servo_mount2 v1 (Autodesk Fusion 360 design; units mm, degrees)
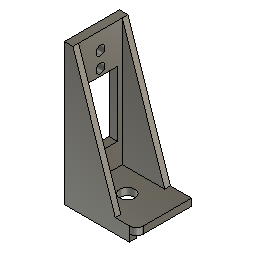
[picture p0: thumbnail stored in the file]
sketch "Sketch1" plane through (0, 0, 0) normal (0, 0, 1) x axis (1, 0, 0)
  line L1 (-10.25, 8.5) -> (10.25, 8.5)
  line L2 (-10.25, -8.5) -> (-10.25, 8.5)
  line L3 (10.25, -8.5) -> (-10.25, -8.5)
  line L4 (10.25, 8.5) -> (10.25, -8.5)
  line L5 (-10.25, -8.5) -> (10.25, 8.5)
  line L6 (10.25, -8.5) -> (-10.25, 8.5)
  point P6 (0, 0)
  point P1 (0, 0)
  point P2 (10.25, 8.5)
  point P5 (10.25, -8.5)
  point P4 (-10.25, -8.5)
  horizontal L1
  perpendicular L1 L2
  parallel L1 L3
  parallel L2 L4
  coincident L5 P6
  coincident L6 P6
  coincident P1 P6
  dimension "d1" distance P2 P5 = 17
  dimension "d2" distance P4 P5 = 20.5
extrude "Extrude1" new body sketch "Sketch1" profile of L1 L2 L3 L4 along normal blind 2.5
shell "Shell1" outerThickness 2.5
fillet "Fillet1" radius 2.5 1
sketch "Sketch2" plane through (0, 0, 2.5) normal (0, 0, -1) x axis (1, 0, 0)
  line L1 (-10.25, -8.5) -> (-10.25, 7.5)
  line L2 (10.25, -8.5) -> (-10.25, -8.5)
  line L3 (10.25, 7.5) -> (10.25, -8.5)
  line L4 (-9.25, 8.5) -> (9.25, 8.5)
  arc A1 centre (-9.25, 7.5) radius 1 clockwise from (-10.25, 7.5) to (-9.25, 8.5)
  arc A2 centre (9.25, 7.5) radius 1 clockwise from (9.25, 8.5) to (10.25, 7.5)
  circle C1 centre (0, 1.5) radius 2.7
  point P1 (0, 0)
  point P10 (0, 1.5)
  vertical P1 P10
  dimension "d10" diameter C1 = 5.4
  dimension "d11" distance L4 P10 = 7
extrude "Extrude2" cut sketch "Sketch2" profile of C1 against normal blind 7
sketch "Sketch3" plane through (-12.75, 0, 0) normal (-1, 0, 0) x axis (0, -1, 0)
  line L1 (11, 0) -> (-8.5, 0)
  line L2 (11, 5) -> (11, 0)
  line L3 (-8.5, 5) -> (11, 5)
  line L4 (-8.5, 0) -> (-8.5, 5)
  line L5 (-8.5, 5) -> (11, 5)
  line L6 (-8.5, 50) -> (-8.5, 5)
  line L7 (11, 50) -> (-8.5, 50)
  line L8 (11, 5) -> (11, 50)
  point P4 (11, 5)
  point P6 (11, 5)
  point P5 (-8.5, 5)
  point P7 (-8.5, 5)
  point P9 (11, 50)
  horizontal L5
  vertical L6
  horizontal L7
  vertical L8
  coincident P4 P6
  coincident P5 P7
  dimension "d14" distance P6 P9 = 45
extrude "Extrude3" add sketch "Sketch3" profile of L3 L5 L6 L7 L8 against normal blind 3
sketch "Sketch4" plane through (0, -11, 0) normal (0, -1, 0) x axis (1, 0, 0)
  line L1 (10.25, 5) -> (10.25, 0)
  line L2 (-9.75, 5) -> (10.25, 5)
  line L3 (-9.75, 50) -> (-9.75, 5)
  line L4 (-12.75, 50) -> (-9.75, 50)
  line L5 (-12.75, 0) -> (-12.75, 50)
  line L6 (10.25, 0) -> (-12.75, 0)
  line L7 (-9.75, 50) -> (5.25, 5)
  point P8 (5.25, 5)
  point P5 (-9.75, 50)
  point P9 (-9.75, 50)
  coincident L2 P8
  coincident P5 P9
  dimension "d17" distance P8 P9 = 15
extrude "Extrude4" add sketch "Sketch4" profile of L2 L3 L7 against normal blind 2
sketch "Sketch5" plane through (0, 8.5, 0) normal (0, 1, 0) x axis (-1, 0, 0)
  line L1 (-10.25, 2.5) -> (-10.25, 0)
  line L2 (10.25, 2.5) -> (-10.25, 2.5)
  line L3 (10.25, 0) -> (10.25, 2.5)
  line L4 (12.75, 0) -> (10.25, 0)
  line L5 (12.75, 50) -> (12.75, 0)
  line L6 (9.75, 50) -> (12.75, 50)
  line L7 (9.75, 5) -> (9.75, 50)
  line L8 (-12.75, 5) -> (9.75, 5)
  line L9 (-12.75, 0) -> (-12.75, 5)
  line L10 (-10.25, 0) -> (-12.75, 0)
  line L11 (9.75, 5) -> (-5.25, 5)
  line L12 (9.75, 50) -> (9.75, 5)
  line L13 (-5.25, 5) -> (9.75, 50)
extrude "Extrude5" add sketch "Sketch5" profile of L7 L8 L11 L12 L13 against normal blind 2
sketch "Sketch6" plane through (-9.75, 0, 0) normal (1, 0, 0) x axis (0, 1, 0)
  line L1 (6.5, 50) -> (6.5, 5)
  line L2 (-9, 50) -> (6.5, 50)
  line L3 (-9, 5) -> (-9, 50)
  line L4 (6.5, 5) -> (-9, 5)
  line L5 (4.8, 36) -> (-7.3, 36)
  line L6 (4.8, 13) -> (4.8, 36)
  line L7 (-7.3, 13) -> (4.8, 13)
  line L8 (-7.3, 36) -> (-7.3, 13)
  line L9 (-9, 5) -> (6.5, 5)
  circle C1 centre (-1.25, 38.4) radius 1.6
  circle C2 centre (-1.25, 10.6) radius 1.6
  circle C3 centre (-1.25, 18.9) radius 1.5
  circle C4 centre (-1.25, 43.9) radius 1.6
  point P10 (-1.25, 13)
  point P13 (-1.25, 5)
  point P15 (-1.25, 36)
  point P16 (4.8, 24.5)
  point P14 (-1.25, 38.4)
  point P17 (-1.25, 10.6)
  point P18 (-1.25, 18.9)
  point P19 (-1.25, 43.9)
  point P6 (-7.3, 36)
  point P9 (-7.3, 13)
  point P7 (4.8, 36)
  point P8 (4.8, 13)
  horizontal L5
  vertical L6
  horizontal L7
  vertical L8
  midpoint L7 P10
  midpoint L4 P13
  vertical P10 P13
  midpoint L5 P15
  midpoint L6 P16
  vertical P14 P15
  vertical P10 P17
  vertical P15 P18
  vertical P14 P19
  dimension "d22" distance P6 P9 = 23
  dimension "d23" distance P6 P7 = 12.1
  dimension "d24" distance P10 P13 = 8
  dimension "d27" diameter C1 = 3.2
  dimension "d29" distance P6 P14 = 2.4
  dimension "d30" diameter C2 = 3.2
  dimension "d31" distance P10 P17 = 2.4
  dimension "d32" diameter C3 = 3
  dimension "d34" diameter C4 = 3.2
  dimension "d35" distance P18 P19 = 25
  dimension "d36" distance P8 P18 = 5.9
extrude "Extrude6" cut sketch "Sketch6" profile of L5 L6 L7 L8 C1 C2 C4 against normal blind 14
sketch "Sketch8" plane through (0, 0, 0) normal (0, 0, -1) x axis (1, 0, 0)
  line L1 (-12.75, 11) -> (10.25, 11)
  line L2 (-12.75, -8.5) -> (-12.75, 11)
  line L3 (-10.25, -8.5) -> (-12.75, -8.5)
  line L4 (-10.25, 7.5) -> (-10.25, -8.5)
  line L5 (9.25, 8.5) -> (-9.25, 8.5)
  line L6 (10.25, -8.5) -> (10.25, 7.5)
  line L7 (12.75, -8.5) -> (10.25, -8.5)
  line L8 (12.75, 8.5) -> (12.75, -8.5)
  line L9 (10.25, 8.5) -> (9.25, 8.5)
  line L10 (10.25, 11) -> (10.25, 8.5)
  arc A1 centre (10.25, 8.5) radius 2.5 clockwise from (10.25, 11) to (12.75, 8.5)
  arc A2 centre (-9.25, 7.5) radius 1 clockwise from (-10.25, 7.5) to (-9.25, 8.5)
  arc A3 centre (9.25, 7.5) radius 1 clockwise from (9.25, 8.5) to (10.25, 7.5)
  point P11 (9.25, 8.5)
  point P16 (9.25, 8.5)
  point P4 (10.25, 8.5)
  point P17 (10.25, 8.5)
  point P3 (10.25, 11)
  point P18 (10.25, 11)
  coincident P11 P16
  coincident P4 P17
  coincident P3 P18
extrude "Extrude7" cut sketch "Sketch8" profile of A1 A3 L6 L7 L8 L9 L10 to an object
